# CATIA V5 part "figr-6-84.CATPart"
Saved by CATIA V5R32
Part number: Part1
Bounding box of the stored display mesh (mm): x -270.425 to 270.571, y -147 to 147, z 0 to 119.904
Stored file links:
  D:\PROJECTS\Project 2022\CATIA V5 6R 2022\Resources\Part Files\c06_catia_v5_6r2022_prt\figr-6-84.CATPart
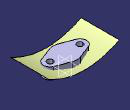
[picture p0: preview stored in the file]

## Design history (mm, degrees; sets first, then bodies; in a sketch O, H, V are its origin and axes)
Body1 (main body)
  Sketch1 on xy-plane, origin (0, 0, 0), H (1, 0, 0), V (0, 1, 0)
    arc A1 centre (0, 0) radius 91.6528 from (-32.9557, -85.5228) to (32.9557, -85.5228) ccw
    point P1 (0, 91.6528)
    arc A2 centre (-114.4606, 0) radius 50.4961 from (-132.6175, 47.1188) to (-132.6175, -47.1188) ccw
    point P2 (-114.4606, 0)
    arc A3 centre (114.4606, 0) radius 50.4961 from (132.6175, 47.1188) to (132.6175, -47.1188) cw
    line L1 (-132.6175, 47.1188) -> (-32.9557, 85.5228)
    point P4 (-132.6175, 47.1188)
    point P5 (-32.9557, 85.5228)
    line L2 (-132.6175, -47.1188) -> (-32.9557, -85.5228)
    point P6 (-132.6175, -47.1188)
    point P7 (-32.9557, -85.5228)
    point P8 (32.9557, -85.5228)
    point P9 (132.6175, -47.1188)
    line L3 (132.6175, -47.1188) -> (32.9557, -85.5228)
    point P10 (32.9557, 85.5228)
    point P11 (132.6175, 47.1188)
    line L4 (132.6175, 47.1188) -> (32.9557, 85.5228)
    point P12 (-32.9557, -85.5228)
    point P13 (32.9557, -85.5228)
    arc A4 centre (0, 0) radius 91.6528 from (32.9557, 85.5228) to (-32.9557, 85.5228) ccw
    circle A5 centre (-114.4606, 0) radius 22.8078
    circle A6 centre (114.4606, 0) radius 22.8078
    coincidence: A1 P1, P1 V, P2 H, P7 A1, L2 P12, L3 P13, A1 A4, P7 P12, P8 P13
    symmetry: A2 A3 V, P7 P8 V, P6 P9 V, L2 L3 V, P5 P10 V, P4 P11 V, L1 L4 V
    tangency: L1 A1, L1 A2, A2 L2, A1 L2, L3 A1, A5 A1, A6 A1
  Pad1: profile Sketch1, direction (0, 0, 1), length 87
  Sketch2 on zx-plane, origin (0, 0, 0), H (-1, 0, 0), V (0, 0, 1)
    spline S1 through (-270.5707, 119.9036) (-20.9781, 45.6362) (270.425, 111.0056)
  Extrude1: Element1 Sketch2, Lim1 -147, Lim2 -147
